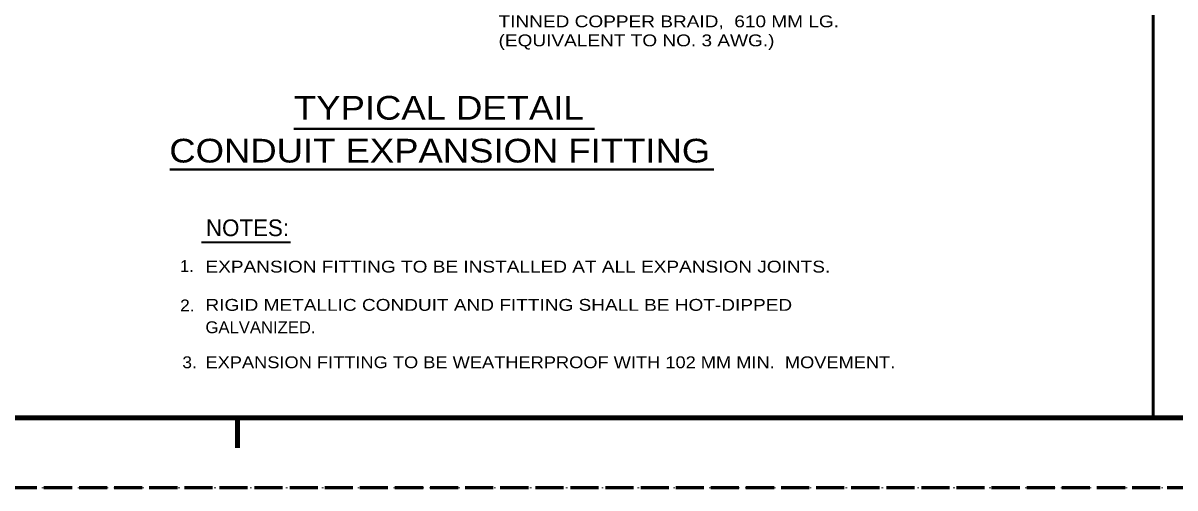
# Model space of a CAD drawing. Extents: x 312583 to 312854, y 144419 to 144597.
# Drawn here: x 312713.6 to 312787.5, y 144418.6 to 144448.4 of the extents above; entities that cross this region are included whole.
import ezdxf
from ezdxf.enums import TextEntityAlignment as Align

# ---------------------------------------------------------------- set-up
doc = ezdxf.new("R2010")
doc.units = 0
doc.header["$LTSCALE"] = 0.3
doc.linetypes.add('DOTTED', pattern=[1.5, 0.3, -1.2])
doc.linetypes.add('LONG_DASHED', pattern=[7.5, 6, -1.5])
doc.layers.add('1', color=7, linetype='Continuous', lineweight=13)

msp = doc.modelspace()

# ---------------------------------------------------------------- linework, layer by layer
at = {"layer": '1', "lineweight": 53}
msp.add_line((312786.0518, 144423.0846), (312786.0518, 144482.0146), dxfattribs=at)
at = {"layer": '1', "lineweight": 40}
for p, q in [((312730.9612, 144441.6098), (312750.2373, 144441.6098)), ((312723.0239, 144439.0031), (312757.8911, 144439.0031))]:
    msp.add_line(p, q, dxfattribs=at)
at = {"layer": '1', "lineweight": 35}
msp.add_line((312725.0389, 144434.3341), (312730.7506, 144434.3341), dxfattribs=at)
at = {"layer": '1', "lineweight": 158}
for p, q in [((312616.5, 144423.0846), (312849, 144423.0846)), ((312727.35, 144421.1646), (312727.35, 144423.0846))]:
    msp.add_line(p, q, dxfattribs=at)
at = {"layer": '1', "linetype": 'LONG_DASHED', "lineweight": 60}
msp.add_line((312851.75, 144418.5846), (312583.526, 144418.5846), dxfattribs=at)
at = {"layer": '1', "linetype": 'DOTTED'}
msp.add_line((312601.2, 144418.5846), (312853.5, 144418.5846), dxfattribs=at)

# ---------------------------------------------------------------- texts
at = {"layer": '1'}
for s, width, p in [('TINNED COPPER BRAID,  610 MM LG.', 1.2, (312744.0903, 144448.1198)), ('(EQUIVALENT TO NO. 3 AWG.)', 1.2, (312744.0903, 144446.8998)), ('1.   ', 1.05, (312723.6644, 144432.431)), ('EXPANSION FITTING TO BE INSTALLED AT ALL EXPANSION JOINTS.', 1.2, (312725.3015, 144432.3955)), ('2.  ', 1.1, (312723.675, 144429.9068)), ('RIGID METALLIC CONDUIT AND FITTING SHALL BE HOT-DIPPED', 1.2, (312725.3015, 144429.9422)), ('GALVANIZED.', 1.05, (312725.3015, 144428.5085)), ('3.  ', 1.1, (312723.8167, 144426.2622)), ('EXPANSION FITTING TO BE WEATHERPROOF WITH 102 MM MIN.  MOVEMENT.', 1.15, (312725.3015, 144426.2622))]:
    msp.add_text(s, height=0.76, dxfattribs=dict(at, width=width)).set_placement(p)
at = {"layer": '1', "width": 1.15}
for s, p in [('TYPICAL DETAIL', (312740.2614, 144442.1984)), ('CONDUIT EXPANSION FITTING', (312740.3206, 144439.4499))]:
    msp.add_text(s, height=1.52, dxfattribs=at).set_placement(p, align=Align.CENTER)
at = {"layer": '1'}
msp.add_text('NOTES:', height=1.07, dxfattribs=at).set_placement((312727.9944, 144434.7305), align=Align.CENTER)

doc.saveas('drawing.dxf')
